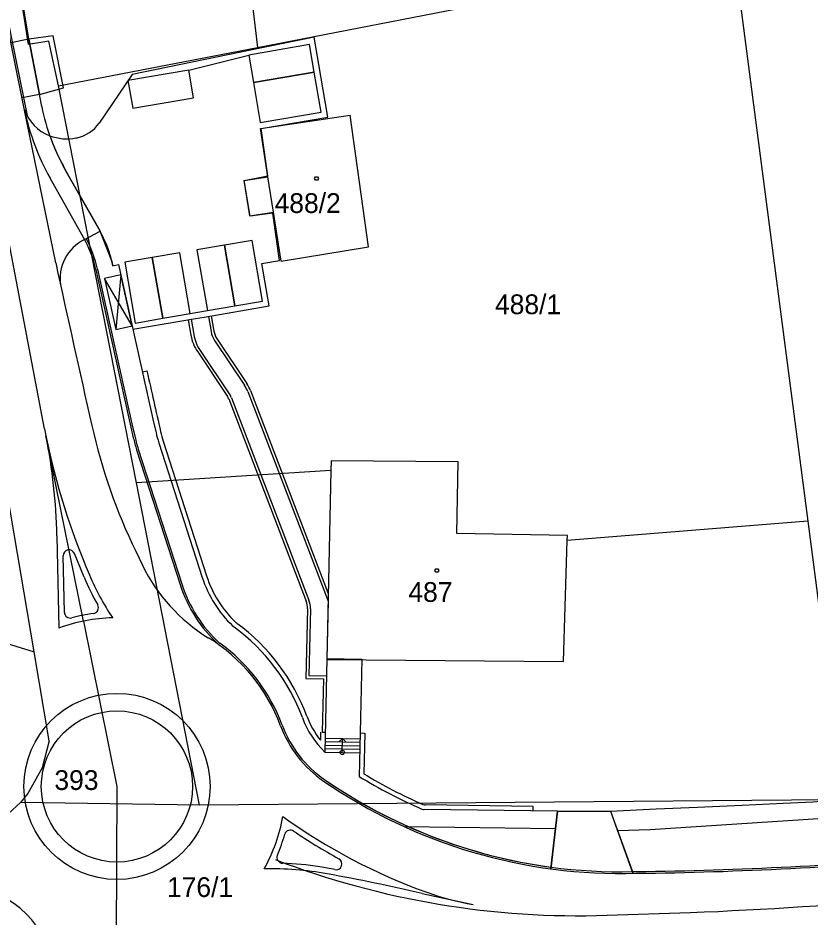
# Model space of a CAD drawing. Extents: x -639621 to -639329, y -1192893 to -1192488.
# Drawn here: x -639501.1 to -639433, y -1192724.9 to -1192647.6 of the extents above; entities that cross this region are included whole.
import ezdxf

# ---------------------------------------------------------------- set-up
doc = ezdxf.new("R2010")
doc.units = 0
for name, color, linetype in [('Vrstva 1', 7, 'Continuous'), ('Vrstva 19', 7, 'Continuous'), ('Vrstva 2', 7, 'Continuous'), ('Vrstva 20', 7, 'Continuous'), ('Vrstva 22', 7, 'Continuous'), ('Vrstva 4', 7, 'Continuous'), ('Vrstva 5', 7, 'Continuous')]:
    doc.layers.add(name, color=color, linetype=linetype)

msp = doc.modelspace()

# ---------------------------------------------------------------- linework, layer by layer
at = {"layer": 'Vrstva 1'}
for p, q in [((-639500.18, -1192649.88), (-639502.88, -1192633.13)), ((-639499.71, -1192702.08), (-639511.27, -1192634.08)), ((-639439.54, -1192642.21), (-639433.22, -1192690.86)), ((-639480.96, -1192646.31), (-639480.51, -1192650.14)), ((-639480.51, -1192650.14), (-639460.43, -1192646.25)), ((-639498.43, -1192649.61), (-639500.18, -1192649.88)), ((-639497.61, -1192653.45), (-639498.43, -1192649.61)), ((-639497.61, -1192653.45), (-639480.51, -1192650.14)), ((-639490.92, -1192687.58), (-639497.61, -1192653.45)), ((-639480.26, -1192657.1), (-639472.54, -1192655.97)), ((-639470.96, -1192667.29), (-639472.54, -1192655.97)), ((-639479.61, -1192661.25), (-639480.26, -1192657.1)), ((-639481.67, -1192661.58), (-639479.61, -1192661.25)), ((-639481.67, -1192661.58), (-639481.19, -1192664.63)), ((-639481.19, -1192664.63), (-639479.13, -1192664.31)), ((-639478.46, -1192668.51), (-639479.13, -1192664.31)), ((-639478.46, -1192668.51), (-639470.96, -1192667.29)), ((-639474.18, -1192685.67), (-639474.2, -1192686.51)), ((-639463.27, -1192685.77), (-639474.18, -1192685.67)), ((-639463.37, -1192691.93), (-639463.27, -1192685.77)), ((-639474.2, -1192686.51), (-639490.92, -1192687.58)), ((-639485.5, -1192715.26), (-639490.92, -1192687.58)), ((-639433.22, -1192690.86), (-639453.88, -1192692.51)), ((-639433.22, -1192690.86), (-639430.11, -1192714.81)), ((-639453.87, -1192692.08), (-639463.37, -1192691.93)), ((-639453.88, -1192692.51), (-639453.87, -1192692.08)), ((-639504.3, -1192700.68), (-639499.71, -1192702.08)), ((-639498.41, -1192709.74), (-639499.71, -1192702.08)), ((-639498.41, -1192709.74), (-639499.01, -1192712.06)), ((-639499.01, -1192712.06), (-639500.24, -1192714.27)), ((-639500.24, -1192714.27), (-639500.89, -1192715.05)), ((-639500.89, -1192715.05), (-639501.93, -1192716.01)), ((-639485.5, -1192715.26), (-639500.89, -1192715.05)), ((-639430.11, -1192714.81), (-639485.5, -1192715.26))]:
    msp.add_line(p, q, dxfattribs=at)
at = {"layer": 'Vrstva 19'}
for p, q in [((-639500.522, -1192655.528), (-639503.63, -1192640.243)), ((-639497.852, -1192668.663), (-639500.522, -1192655.528)), ((-639496.11, -1192657.92), (-639496.015, -1192657.901)), ((-639494.154, -1192665.729), (-639497.026, -1192660.652)), ((-639495.46, -1192666.467), (-639498.331, -1192661.391)), ((-639490.895, -1192684.727), (-639487.163, -1192696.306)), ((-639495.415, -1192695.663), (-639496.243, -1192693.636)), ((-639490.974, -1192693.449), (-639490.394, -1192694.648)), ((-639497.104, -1192698.702), (-639497.207, -1192693.836)), ((-639495.468, -1192699.452), (-639492.588, -1192713.663)), ((-639492.588, -1192713.663), (-639492.665, -1192728.163)), ((-639450.17, -1192715.78), (-639448.23, -1192721.15))]:
    msp.add_line(p, q, dxfattribs=at)
for points in [[(-639498.81, -1192682.926), (-639506.825, -1192640.839)], [(-639495.468, -1192699.452), (-639498.583, -1192684.08)], [(-639497.743, -1192692.111), (-639497.574, -1192700.047)], [(-639466.365, -1192722.875), (-639461.978, -1192723.807)], [(-639450.462, -1192724.741), (-639443.332, -1192724.506)]]:
    msp.add_lwpolyline(points, dxfattribs=at)
for radius in [8, 6.5]:
    msp.add_circle((-639492.588, -1192713.663), radius, dxfattribs=at)
for centre, radius, start, end in [((-639480.923, -1192651.544), 20, 191.49158, 209.49575), ((-639493.725, -1192670.01), 3.745, 115.94138, 189.86951), ((-639504.164, -1192671.391), 10, 12.4113, 29.49575), ((-636647.693, -1192042.764), 2918.074, 192.385621, 192.66671), ((-636647.689, -1192042.763), 2914.828, 192.411302, 192.702157), ((-639400.575, -1192664.219), 100, 190.78189, 191.45585), ((-639445.964, -1192671.674), 50, 192.66671, 205.81751), ((-639438.922, -1192671.354), 61, 191.52172, 203.29127), ((-639546.176, -1192693.139), 48.444, 1.21588, 11.43039), ((-639479.474, -1192681.046), 12, 192.70216, 197.86674), ((-639496.706, -1192693.826), 0.5, 22.24955, 181.21473), ((-639476.903, -1192688.091), 15, 205.92212, 238.47634), ((-639476.903, -1192688.091), 20, 202.24905, 209.88446), ((-639476.903, -1192688.091), 19.5, 202.24905, 214.61422), ((-639475.742, -1192692.624), 12, 197.86674, 227.52419), ((-639494.677, -1192698.305), 0.5, 277.74461, 29.88446), ((-639492.588, -1192713.663), 14.5, 91.43484, 110.11396), ((-639496.604, -1192698.693), 0.5, 181.20925, 285.01553), ((-639492.588, -1192713.663), 15, 97.74349, 105.01461), ((-639492.588, -1192713.663), 15, 20.36264, 58.47634), ((-639469.15, -1192704.964), 10, 200.36264, 235.41597), ((-639449.284, -1192676.149), 45, 235.41597, 271.68118), ((-639492.588, -1192713.663), 14.5, 330.72784, 349.76539), ((-639449.284, -1192676.149), 49.5, 234.0867, 250.32239), ((-639492.588, -1192713.663), 15, 336.81317, 344.10421), ((-639477.681, -1192717.909), 0.5, 55.78391, 164.10421), ((-639449.284, -1192676.149), 50, 235.78391, 241.01466), ((-639452.868, -1192651.78), 73, 249.0487, 271.88891), ((-639478.34, -1192719.766), 0.5, 156.81317, 267.92616), ((-639473.756, -1192720.324), 0.5, 258.19186, 61.01466), ((-639451.835, -1192385.666), 335.486, 270.66119, 275.20289), ((-639479.382, -1192748.546), 27.799, 79.93893, 91.14847), ((-639479.382, -1192748.546), 28.299, 81.37243, 87.92616), ((-639481.925, -1192759.399), 39.42, 78.19186, 80.08536), ((-639499.303, -1192860.56), 141.57, 76.54628, 79.92036), ((-639460.643, -1192306.466), 418.398, 272.37127, 277.67067), ((-639506.015, -1192730.304), 8, 9.47307, 90.86714), ((-639457.831, -1192700.049), 24.118, 250.32238, 260.0975)]:
    msp.add_arc(centre, radius, start, end, dxfattribs=at)
at = {"layer": 'Vrstva 20'}
for p, q in [((-639500.248, -1192656.125), (-639503.483, -1192640.213)), ((-639500.159, -1192649.442), (-639501.697, -1192649.752)), ((-639499.052, -1192655.229), (-639500.15, -1192649.44)), ((-639500.149, -1192649.44), (-639499.248, -1192654.198)), ((-639486.416, -1192652.094), (-639481.262, -1192650.792)), ((-639499.248, -1192654.198), (-639497.18, -1192653.62)), ((-639499.248, -1192654.198), (-639500.739, -1192654.462)), ((-639495.363, -1192666.642), (-639494.043, -1192665.93)), ((-639493.053, -1192668.423), (-639494.043, -1192665.93)), ((-639492.932, -1192668.919), (-639492.444, -1192668.812)), ((-639492.252, -1192669.679), (-639492.695, -1192674.386)), ((-639491.279, -1192674.072), (-639493.668, -1192669.992)), ((-639486.292, -1192673.018), (-639484.813, -1192672.764)), ((-639486.454, -1192673.553), (-639486.228, -1192674.868)), ((-639486.207, -1192673.511), (-639485.981, -1192674.826)), ((-639484.729, -1192673.257), (-639484.503, -1192674.572)), ((-639484.482, -1192673.215), (-639484.257, -1192674.53)), ((-639483.986, -1192675.207), (-639481.422, -1192679.041)), ((-639484.194, -1192675.346), (-639481.629, -1192679.18)), ((-639485.649, -1192676.319), (-639483.084, -1192680.153)), ((-639485.441, -1192676.18), (-639482.876, -1192680.014)), ((-639490.398, -1192678.037), (-639490.008, -1192677.95)), ((-639488.992, -1192684.114), (-639485.26, -1192695.692)), ((-639488.611, -1192683.991), (-639484.879, -1192695.569)), ((-639490.753, -1192684.681), (-639487.02, -1192696.26)), ((-639474.431, -1192697.068), (-639474.439, -1192697.747)), ((-639474.553, -1192702.67), (-639474.724, -1192710.703)), ((-639474.553, -1192702.67), (-639471.552, -1192702.72)), ((-639471.552, -1192702.72), (-639471.769, -1192712.802)), ((-639476.087, -1192704.135), (-639474.584, -1192704.167)), ((-639474.84, -1192704.412), (-639474.938, -1192708.998)), ((-639475.088, -1192708.995), (-639475.102, -1192709.69)), ((-639474.938, -1192708.998), (-639474.688, -1192709.004)), ((-639471.689, -1192709.068), (-639471.289, -1192709.077)), ((-639471.289, -1192709.077), (-639471.364, -1192712.58)), ((-639474.705, -1192709.804), (-639471.706, -1192709.868)), ((-639474.698, -1192709.504), (-639471.699, -1192709.568)), ((-639473.199, -1192709.536), (-639473.505, -1192709.829)), ((-639473.224, -1192710.736), (-639473.199, -1192709.536)), ((-639473.199, -1192709.536), (-639472.905, -1192709.842)), ((-639474.724, -1192710.703), (-639471.725, -1192710.768)), ((-639474.717, -1192710.403), (-639471.719, -1192710.468)), ((-639474.711, -1192710.104), (-639471.712, -1192710.168)), ((-639456.818, -1192715.373), (-639466.092, -1192715.251)), ((-639456.823, -1192715.773), (-639456.818, -1192715.373)), ((-639454.73, -1192715.8), (-639466.177, -1192715.65)), ((-639454.73, -1192715.8), (-639455.303, -1192720.745)), ((-639454.904, -1192717.298), (-639467.878, -1192717.128))]:
    msp.add_line(p, q, dxfattribs=at)
for points in [[(-639500.159, -1192649.441), (-639500.159, -1192649.441), (-639502.989, -1192632.471), (-639506.38, -1192612.72), (-639506.699, -1192611.025)], [(-639493.053, -1192668.423), (-639492.932, -1192668.919), (-639492.444, -1192668.812), (-639491.212, -1192674.369), (-639485.838, -1192673.447), (-639485.098, -1192673.32), (-639479.505, -1192672.361), (-639480.13, -1192668.721), (-639478.61, -1192668.46), (-639479.189, -1192664.375), (-639481.15, -1192664.65), (-639481.66, -1192661.57), (-639479.62, -1192661.17), (-639480.18, -1192657.1), (-639474.463, -1192656.123), (-639475.639, -1192649.269), (-639480.958, -1192650.354), (-639491.279, -1192652.46), (-639494.129, -1192656.648)], [(-639481.262, -1192650.792), (-639480.856, -1192653.158), (-639475.633, -1192652.261), (-639476.039, -1192649.896), (-639481.262, -1192650.792)], [(-639491.64, -1192652.991), (-639491.234, -1192655.356), (-639486.01, -1192654.46), (-639486.416, -1192652.094), (-639491.64, -1192652.991)], [(-639480.856, -1192653.158), (-639480.265, -1192656.607), (-639475.041, -1192655.711), (-639475.633, -1192652.261), (-639480.856, -1192653.158)], [(-639497.026, -1192660.652), (-639496.428, -1192661.709), (-639494.666, -1192664.824), (-639494.043, -1192665.93)], [(-639480.979, -1192666.729), (-639483.344, -1192667.135), (-639482.448, -1192672.358), (-639480.082, -1192671.952), (-639480.979, -1192666.729)], [(-639483.344, -1192667.135), (-639485.71, -1192667.54), (-639484.813, -1192672.764), (-639482.448, -1192672.358), (-639483.344, -1192667.135)], [(-639489.553, -1192668.2), (-639491.919, -1192668.606), (-639491.023, -1192673.83), (-639488.657, -1192673.424), (-639489.553, -1192668.2)], [(-639487.188, -1192667.794), (-639489.553, -1192668.2), (-639488.657, -1192673.424), (-639486.292, -1192673.018), (-639487.188, -1192667.794)], [(-639481.348, -1192679.724), (-639474.439, -1192697.747), (-639474.553, -1192702.67)], [(-639481.114, -1192679.634), (-639474.431, -1192697.068)], [(-639482.982, -1192680.35), (-639476.32, -1192697.73)], [(-639482.748, -1192680.261), (-639476.086, -1192697.64)], [(-639476.204, -1192698.396), (-639476.343, -1192704.379), (-639474.84, -1192704.412)], [(-639475.954, -1192698.402), (-639476.087, -1192704.135)], [(-639450.17, -1192715.78), (-639446.251, -1192715.6), (-639442.686, -1192715.436), (-639438.854, -1192715.259), (-639435.328, -1192715.097), (-639432.772, -1192714.98), (-639430.975, -1192714.853), (-639429.271, -1192714.692), (-639424.432, -1192714.231), (-639421.28, -1192713.93)], [(-639449.562, -1192717.463), (-639446.75, -1192717.35), (-639431.85, -1192716.39), (-639422.84, -1192715.45), (-639421.25, -1192716.08)], [(-639455.303, -1192720.745), (-639454.73, -1192715.8), (-639450.17, -1192715.78), (-639448.235, -1192721.137)]]:
    msp.add_lwpolyline(points, dxfattribs=at)
msp.add_lwpolyline([(-639492.252, -1192669.679), (-639493.668, -1192669.992), (-639492.695, -1192674.386), (-639491.279, -1192674.072)], close=True, dxfattribs=at)
msp.add_circle((-639473.224, -1192710.736), 0.185, dxfattribs=at)
for centre, radius, start, end in [((-639497.144, -1192654.382), 3.56, 197.69747, 250.04224), ((-639480.923, -1192651.544), 18.5, 191.49158, 209.49575), ((-639496.609, -1192654.96), 3, 281.41054, 325.76523), ((-639496.907, -1192653.973), 4.027, 248.8581, 281.41054), ((-639480.85, -1192651.51), 18.581, 199.55221, 209.47406), ((-639504.164, -1192671.391), 11.5, 12.4113, 29.49575), ((-639502.453, -1192670.712), 9.675, 13.68266, 29.6226), ((-639504.164, -1192671.391), 10.15, 12.4113, 28.35124), ((-636647.689, -1192042.763), 2912.828, 192.411302, 192.702157), ((-636647.688, -1192042.763), 2914.679, 192.411302, 192.702157), ((-639482.532, -1192674.234), 3.75, 189.73637, 213.78452), ((-639482.532, -1192674.234), 3.5, 189.73637, 213.78452), ((-639482.532, -1192674.234), 2, 189.73637, 213.78452), ((-639482.532, -1192674.234), 1.75, 189.73637, 213.78528), ((-636647.689, -1192042.763), 2912.428, 192.597182, 192.702157), ((-639483.915, -1192680.709), 3, 20.99114, 33.78452), ((-639483.915, -1192680.709), 2.75, 20.99114, 33.78452), ((-639483.915, -1192680.709), 1, 20.99114, 33.78452), ((-639483.915, -1192680.709), 1.25, 20.99114, 33.78452), ((-639479.474, -1192681.046), 11.85, 192.70216, 197.86674), ((-639479.474, -1192681.046), 10, 192.70216, 197.86674), ((-639479.474, -1192681.046), 9.6, 192.70216, 197.86674), ((-639475.742, -1192692.624), 10, 197.86674, 226.35442), ((-639475.742, -1192692.624), 9.6, 197.86674, 226.35442), ((-639475.742, -1192692.624), 11.85, 197.86674, 227.52419), ((-639477.954, -1192698.356), 2, 358.67525, 20.97286), ((-639477.954, -1192698.356), 1.75, 358.67525, 20.97286), ((-639481.678, -1192698.847), 1.4, 226.35442, 233.63178), ((-639492.588, -1192713.663), 17, 20.36264, 53.63178), ((-639481.678, -1192698.847), 1, 226.35442, 233.63178), ((-639492.588, -1192713.663), 17.4, 20.36264, 53.63178), ((-639492.588, -1192713.663), 15.15, 20.36264, 54.31324), ((-639469.15, -1192704.964), 7.6, 200.36264, 218.45039), ((-639469.15, -1192704.964), 9.85, 200.36264, 235.41597), ((-639469.15, -1192704.964), 8, 200.36264, 225.83875), ((-639449.284, -1192676.149), 44.85, 235.41597, 262.30922), ((-639449.284, -1192676.149), 44.85, 235.41597, 271.27178), ((-639449.284, -1192676.149), 43, 238.47257, 246.58822), ((-639449.284, -1192676.149), 42.6, 238.78083, 246.47939), ((-639466.085, -1192714.751), 0.5, 246.47939, 269.24971), ((-639466.171, -1192715.15), 0.5, 246.58822, 269.24971), ((-639451.835, -1192385.666), 335.336, 270.66119, 275.20289), ((-639449.284, -1192676.149), 44.85, 271.27178, 271.68118)]:
    msp.add_arc(centre, radius, start, end, dxfattribs=at)
at = {"layer": 'Vrstva 22'}
for p, q in [((-639498.07, -1192649.14), (-639500.149, -1192649.44)), ((-639497.18, -1192653.62), (-639498.07, -1192649.14))]:
    msp.add_line(p, q, dxfattribs=at)
at = {"layer": 'Vrstva 4'}
for p, q in [((-639479.13, -1192664.31), (-639479.61, -1192661.25)), ((-639474.2, -1192686.51), (-639474.54, -1192702.75)), ((-639454.21, -1192702.93), (-639453.88, -1192692.51)), ((-639474.54, -1192702.75), (-639454.21, -1192702.93))]:
    msp.add_line(p, q, dxfattribs=at)
at = {"layer": 'Vrstva 5'}
for points in [[(-639475.35, -1192661.26), (-639475.26, -1192661.41), (-639475.35, -1192661.56), (-639475.53, -1192661.56), (-639475.62, -1192661.41), (-639475.53, -1192661.26)], [(-639465.01, -1192694.95), (-639464.92, -1192695.1), (-639465.01, -1192695.25), (-639465.19, -1192695.25), (-639465.28, -1192695.1), (-639465.19, -1192694.95)]]:
    msp.add_lwpolyline(points, close=True, dxfattribs=at)

# ---------------------------------------------------------------- texts
at = {"layer": 'Vrstva 2'}
for s, p in [('488/2', (-639479.04, -1192664.37)), ('488/1', (-639460.099, -1192673.07)), ('487', (-639467.541, -1192697.8)), ('393', (-639497.965, -1192713.966)), ('176/1', (-639488.289, -1192723.165))]:
    msp.add_text(s, height=1.7, dxfattribs=at).set_placement(p)

doc.saveas('drawing.dxf')
